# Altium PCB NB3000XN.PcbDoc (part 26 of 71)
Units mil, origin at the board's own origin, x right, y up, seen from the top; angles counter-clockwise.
Board outline 9527.56 x 6929.77 mil, 6 copper layers (Top Layer, GND+SHIELD, MidLayer1, MidLayer2, P2 - 3V3+5V0, Bottom Layer), stack 62.375 mil thick; 832 components, 1027 nets, 4655 pads, 4981 vias.
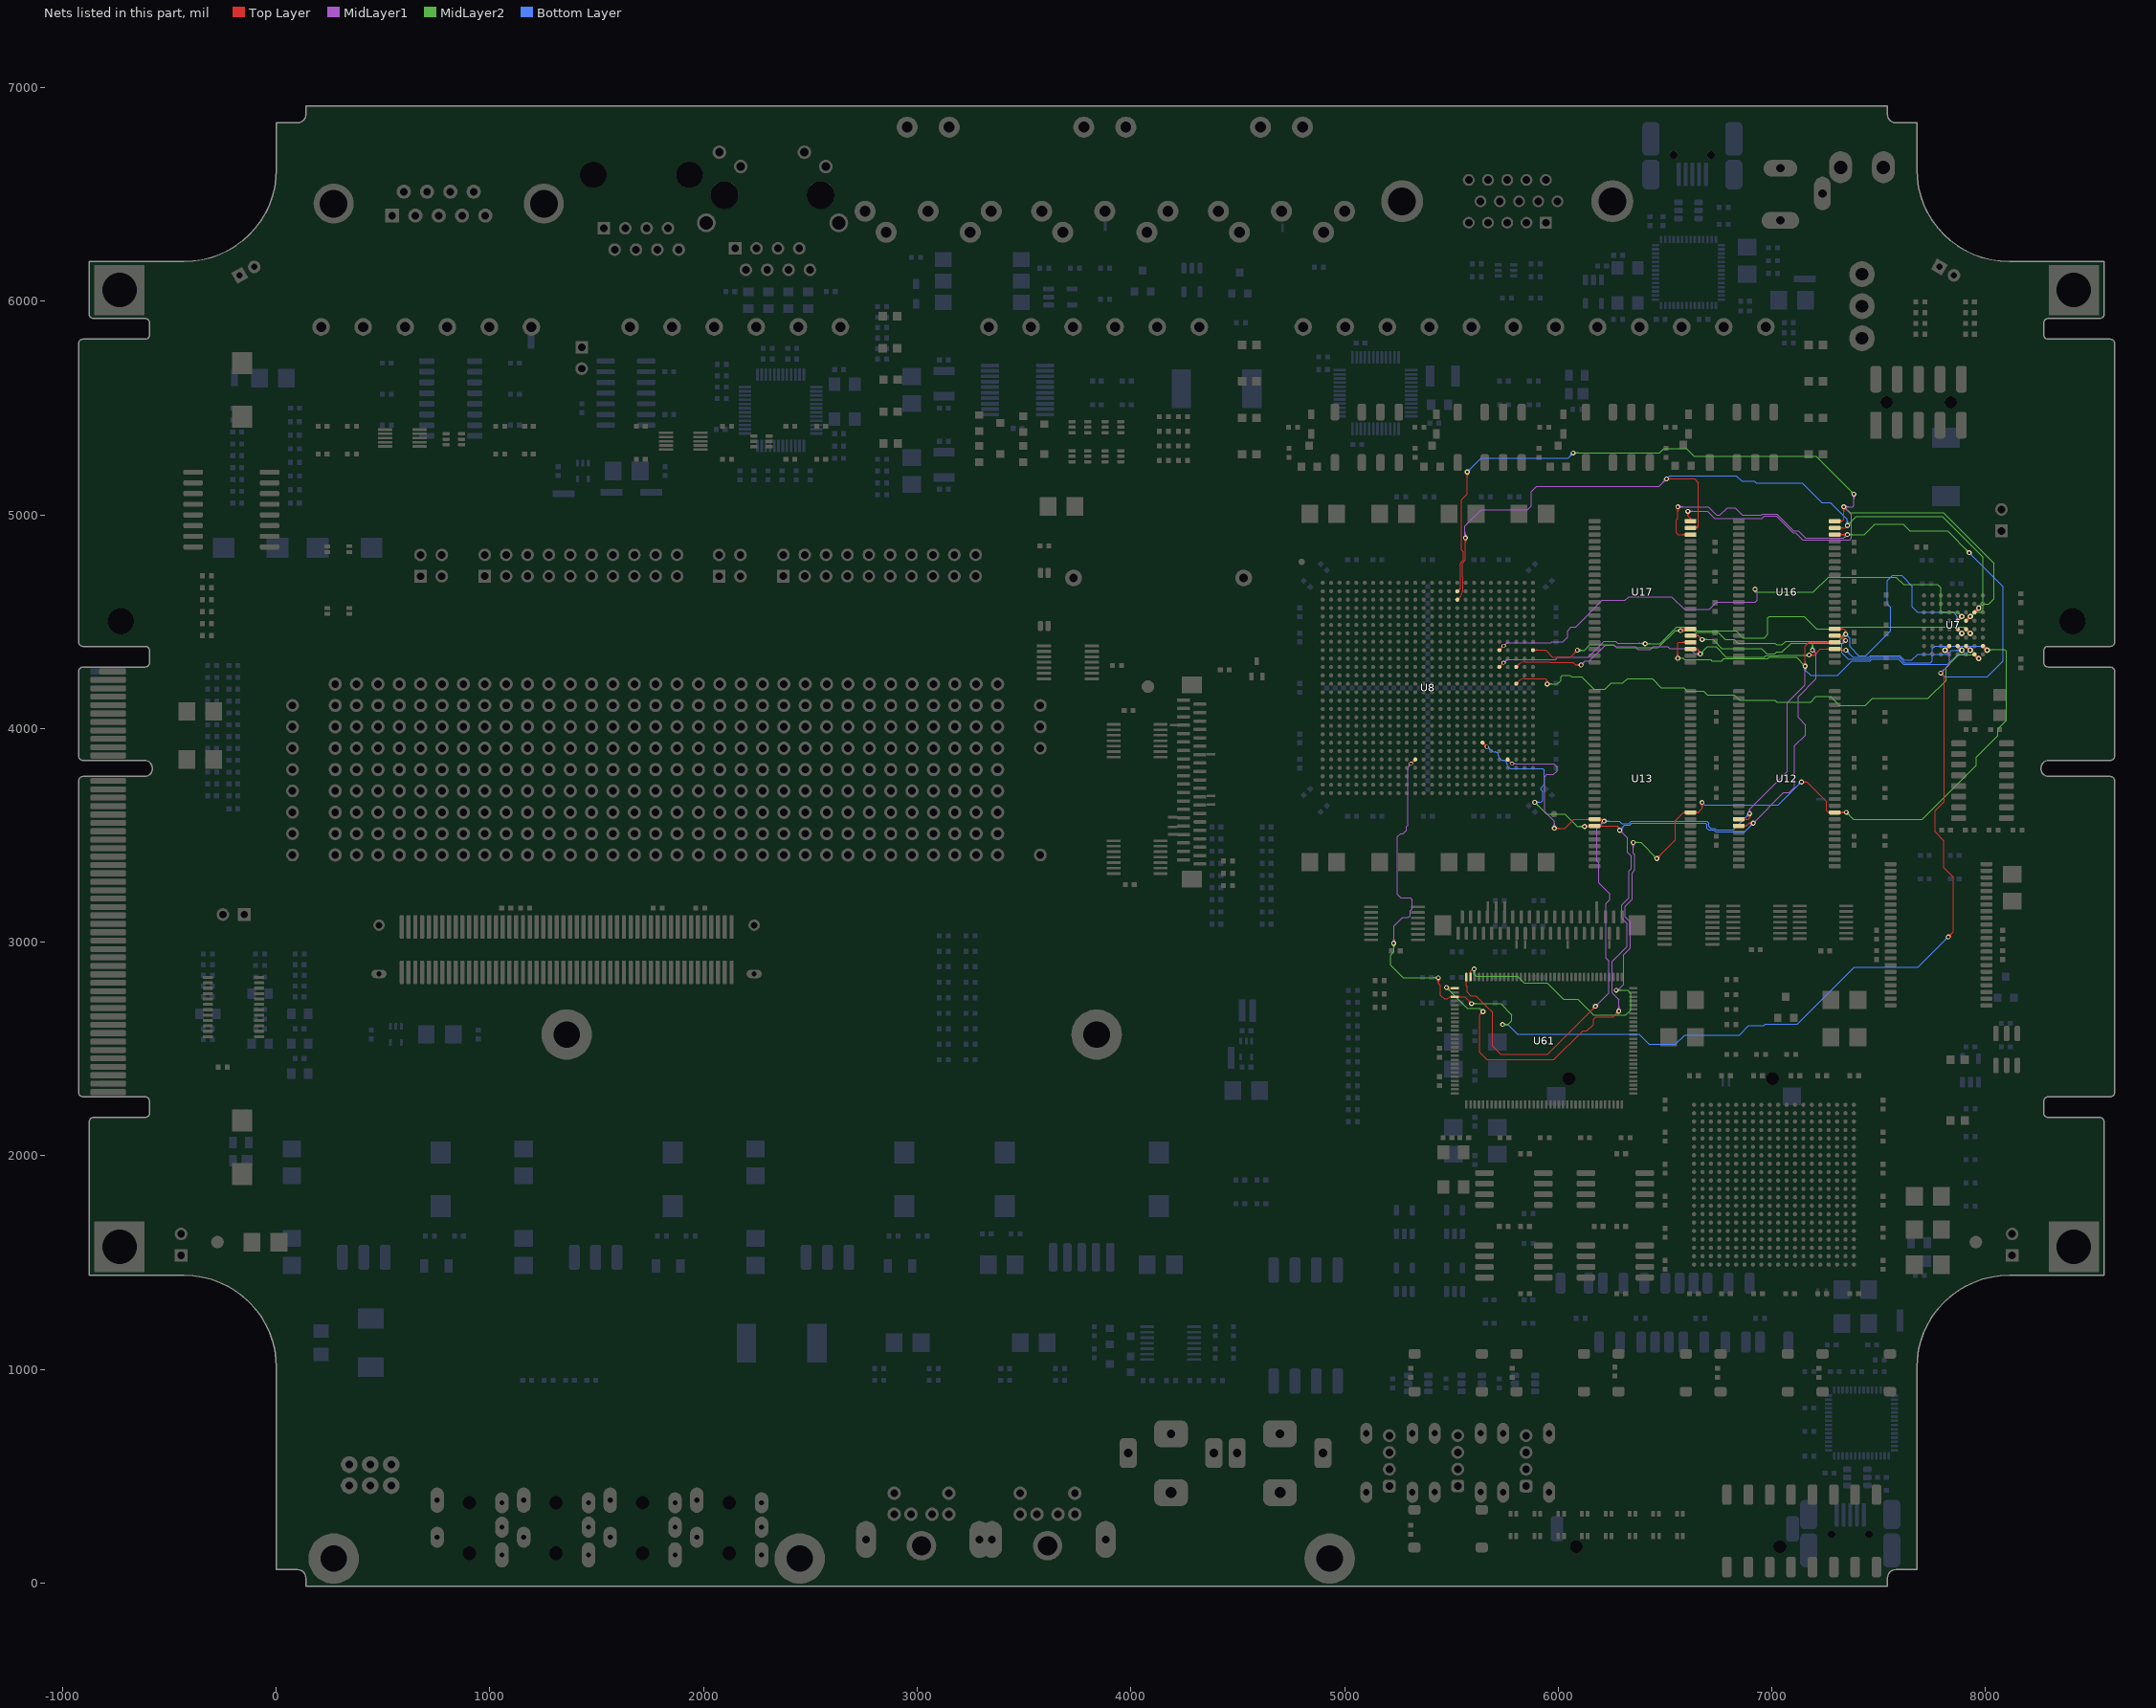
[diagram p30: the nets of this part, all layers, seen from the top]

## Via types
v1: diameter 23, hole 11.81, Top Layer to Bottom Layer, 3672 vias
v2: diameter 26, hole 11.81, Top Layer to Bottom Layer, 461 vias
v3: diameter 19, hole 11.81, Top Layer to Bottom Layer, tented both sides, 396 vias
v4: diameter 23.62, hole 11.81, Top Layer to Bottom Layer, 288 vias
v5: diameter 20, hole 11.81, Top Layer to Bottom Layer, 91 vias
v6: diameter 23, hole 11.81, Top Layer to Bottom Layer, tented both sides, 50 vias
v7: diameter 31, hole 11.81, Top Layer to Bottom Layer, 15 vias
v8: diameter 27.56, hole 11.81, Top Layer to Bottom Layer, tented both sides, 4 vias
v9: diameter 29, hole 11.81, Top Layer to Bottom Layer, 3 vias
v10: diameter 21, hole 11.81, Top Layer to Bottom Layer, 1 vias

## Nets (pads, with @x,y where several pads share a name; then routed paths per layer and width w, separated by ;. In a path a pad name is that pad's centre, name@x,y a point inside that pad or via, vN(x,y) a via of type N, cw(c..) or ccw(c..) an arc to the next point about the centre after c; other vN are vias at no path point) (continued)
DB_MEM.BUS_A14: U7.A7 U8.L24 U12.36 U13.36 U16.25 U17.25 U61.101 | length 8477.1
  Top Layer w4: U61.101@5586.86,2853.36 ccw(c5580.03,2860.19) 5589.69,2860.19 ccw(c5599.34,2860.19) U61.101@5592.51,2853.36 ; U61.101@5589.68,2837.34 5589.69,2866.2 5598.52,2875.04 v1(5606.86,2875.04) ; 5589.98,2866.5 cw(c5600.15,2856.33) v1@5605,2869.86 ; 5594.44,2870.96 cw(c5602.5,2862.9) v1@5606.35,2873.63 ; U8.L24@5803.39,4295.77 ccw(c5803.39,4313.49) 5815.92,4300.96 ; U8.L24@5810.73,4288.43 cw(c5828.45,4288.43) 5815.92,4300.96 ; 5924.74,4312.29 5920,4312.29 ; v1@6100.14,4290.99 ccw(c6083.92,4274.77) 6083.92,4297.71 ccw(c6083.92,4320.64) v1@6100.14,4304.43 ; v1@6102.97,4293.82 ccw(c6093.58,4284.43) 6093.58,4297.71 ccw(c6093.58,4310.99) v1@6102.97,4301.6 ; v1(6106.86,4297.71) 6081.16,4297.71 6070,4308.87 5965.11,4308.87 5961.69,4312.29 5920,4312.29 ; v1(6461.86,3391.71) 6548.52,3478.37 6548.52,3568.52 6587.52,3607.52 ; v1@6461.86,3397.21 ccw(c6461.86,3410.49) 6471.25,3401.1 ccw(c6480.64,3391.71) v1@6467.36,3391.71 ; v1@6461.86,3401.21 ccw(c6461.86,3424.14) 6478.07,3407.93 ccw(c6494.29,3391.71) v1@6471.36,3391.71 ; U13.36@6595.04,3603.32 ccw(c6587.52,3598.69) 6587.52,3607.52 ; U13.36@6595.04,3611.72 cw(c6587.52,3616.35) 6587.52,3607.52 ; U17.25@6619.41,4372.28 6650.95,4372.28 ; U13.36@6642.91,3602.16 cw(c6654.97,3591.27) 6654.97,3607.52 ; U13.36@6642.91,3612.88 ccw(c6654.97,3623.77) 6654.97,3607.52 ; U17.25@6643.87,4368.23 cw(c6650.95,4364.07) 6650.95,4372.28 ; U17.25@6643.87,4376.34 ccw(c6650.95,4380.5) 6650.95,4372.28 ; 6652.31,4370.92 cw(c6634,4352.61) v1@6659.73,4349.67 ; 6658.17,4365.06 cw(c6644.52,4351.41) v1@6663.7,4349.21 ; v1(6665.19,4349.04) 6665.19,4358.04 6650.95,4372.28 ; v1@6666.81,3647.66 cw(c6650.59,3631.44) 6673.52,3631.44 cw(c6696.46,3631.44) v1@6680.24,3647.66 ; v1@6669.64,3650.49 cw(c6660.25,3641.1) 6673.52,3641.1 cw(c6686.8,3641.1) v1@6677.41,3650.49 ; v1(6673.52,3654.37) 6673.52,3626.07 6654.97,3607.52 ; v1(7138.52,3750.04) 7165.19,3750.04 7256.86,3658.37 7256.86,3615.52 7264.86,3607.52 ; v1@7142.41,3746.15 cw(c7151.8,3736.76) 7151.8,3750.04 cw(c7151.8,3763.32) v1@7142.41,3753.93 ; v1@7145.24,3743.32 cw(c7161.46,3727.11) 7161.46,3750.04 cw(c7161.46,3772.98) v1@7145.24,3756.76 ; v1(7174.19,4344.37) 7200,4344.37 7227.91,4372.28 U16.25@7294.41,4372.28 U16.25@7298.52,4372.28 ; v1@7178.08,4340.49 cw(c7187.47,4331.1) 7187.47,4344.37 cw(c7187.47,4357.65) v1@7178.08,4348.26 ; v1@7180.91,4337.66 cw(c7197.13,4321.44) 7197.13,4344.37 cw(c7197.13,4367.31) v1@7180.91,4351.09 ; U12.36@7269.46,3604.45 ccw(c7264.86,3602.53) 7264.86,3607.52 ; U12.36@7269.46,3610.59 cw(c7264.86,3612.51) 7264.86,3607.52 ; U16.25@7271.19,4366.63 ccw(c7257.54,4352.97) 7257.54,4372.28 ccw(c7257.54,4391.6) U16.25@7271.19,4377.94 ; U16.25@7298.52,4366.71 U16.25@7298.52,4372.28 ; U12.36@7317.63,3601.86 cw(c7331.28,3588.21) 7331.28,3607.52 cw(c7331.28,3626.83) U12.36@7317.63,3613.18 ; U16.25@7319.2,4368.86 cw(c7324.61,4366.29) 7324.61,4372.28 ; U16.25@7319.2,4375.71 ccw(c7324.61,4378.28) 7324.61,4372.28 ; 7323.52,3607.52 ccw(c7323.52,3633.37) v1@7341.81,3615.09 ; 7327.65,3607.52 cw(c7327.65,3587.5) v1@7341.81,3601.66 ; 7333.18,3607.52 ccw(c7333.18,3623.72) v1@7344.64,3612.26 ; v1@7337.85,4362.16 ccw(c7330.19,4357.98) 7330.19,4366.71 ; v1@7337.85,4371.26 cw(c7330.19,4375.43) 7330.19,4366.71 ; v1(7346.19,4366.71) 7330.19,4366.71 ; v1(7348.52,3608.37) 7338.19,3608.37 7337.34,3607.52 U12.36@7294.41,3607.52 7264.86,3607.52 ; 5815.92,4300.96 cw(c5843.27,4273.61) 5843.27,4312.29 5910,4312.29 5920,4312.29 ; 6587.52,3607.52 6615,3607.52 6654.97,3607.52 ; U16.25@7298.52,4372.28 7324.62,4372.28 ; 7324.62,4372.28 7330.19,4366.71
  Top Layer w8: U7.A7@7987.8,4380.57 cw(c7987.8,4366.09) 7998.04,4376.33 cw(c8008.28,4386.57) U7.A7@7993.8,4386.57 ; U7.A7@7987.8,4386.57 v2(8007.48,4366.89) ; v2@7998.48,4366.89 ccw(c7976.75,4366.89) 7992.12,4382.25 ccw(c8007.48,4397.62) v2@8007.48,4375.89
  MidLayer1 w4: v1(6106.86,4297.71) 6125.86,4316.71 6146.15,4316.71 6220.48,4391.04 6260.19,4391.04 6268.19,4383.04 6359.86,4383.04 6372.52,4370.37 6431.86,4370.37 6444.86,4383.37 6512.82,4383.37 6521.15,4375.04 6615.19,4375.04 6641.19,4349.04 v1(6665.19,4349.04) ; v1@6106.86,4303.21 ccw(c6106.86,4316.49) 6116.25,4307.1 ccw(c6125.64,4297.71) v1@6112.36,4297.71 ; v1@6106.86,4307.21 ccw(c6106.86,4330.14) 6123.07,4313.93 ccw(c6139.29,4297.71) v1@6116.36,4297.71 ; v1(6271.52,2775.04) 6279.19,2775.04 6306.86,2802.71 6306.86,2942.06 6337.52,2972.73 6337.52,3094 6313.19,3118.34 6313.19,3168.41 6346.86,3202.08 6346.86,3325.04 6359.19,3337.37 6359.19,3409.02 6350.86,3417.35 v1(6350.86,3466.71) ; v1@6344.14,3459.99 cw(c6327.92,3443.77) 6350.86,3443.77 cw(c6373.79,3443.77) v1@6357.57,3459.99 ; v1@6346.97,3462.82 cw(c6337.58,3453.43) 6350.86,3453.43 cw(c6364.14,3453.43) v1@6354.75,3462.82 ; v1@6658.47,4342.32 ccw(c6642.26,4326.11) 6642.26,4349.04 ccw(c6642.26,4371.98) v1@6658.47,4355.76 ; v1@6661.3,4345.15 ccw(c6651.91,4335.76) 6651.91,4349.04 ccw(c6651.91,4362.32) v1@6661.3,4352.93
  MidLayer2 w4: v1@5600.14,2868.32 cw(c5583.92,2852.11) 5606.86,2852.11 cw(c5629.79,2852.11) v1@5613.57,2868.32 ; v1@5602.97,2871.15 cw(c5593.58,2861.76) 5606.86,2861.76 cw(c5620.14,2861.76) v1@5610.75,2871.15 ; v1(5606.86,2875.04) 5606.86,2851.69 5617.17,2841.37 5808.56,2841.37 5841.56,2808.37 5948.52,2808.37 6023.52,2733.37 6091.52,2733.37 6166.52,2658.37 6316.52,2658.37 6340.19,2682.04 6340.19,2758.37 6323.52,2775.04 v1(6271.52,2775.04) ; v1@6275.41,2771.15 cw(c6284.8,2761.76) 6284.8,2775.04 cw(c6284.8,2788.32) v1@6275.41,2778.93 ; v1@6278.24,2768.32 cw(c6294.46,2752.11) 6294.46,2775.04 cw(c6294.46,2797.98) v1@6278.24,2781.76 ; v1(6350.86,3466.71) 6386.86,3466.71 v1(6461.86,3391.71) ; v1@6354.75,3462.82 cw(c6364.14,3453.43) 6364.14,3466.71 cw(c6364.14,3479.99) v1@6354.75,3470.6 ; v1@6357.57,3459.99 cw(c6373.79,3443.77) 6373.79,3466.71 cw(c6373.79,3489.64) v1@6357.57,3473.43 ; v1@6452.36,3391.71 ccw(c6429.42,3391.71) 6445.64,3407.93 ccw(c6461.86,3424.14) v1@6461.86,3401.21 ; v1@6456.36,3391.71 ccw(c6443.08,3391.71) 6452.47,3401.1 ccw(c6461.86,3410.49) v1@6461.86,3397.21 ; v1(6665.19,4349.04) 6699.52,4383.37 6738.19,4383.37 6786.86,4334.71 6965.19,4334.71 6972.19,4341.71 7032.52,4341.71 7035.19,4344.37 v1(7174.19,4344.37) ; v1@6665.19,4354.54 ccw(c6665.19,4367.82) 6674.58,4358.43 ccw(c6683.97,4349.04) v1@6670.69,4349.04 ; v1@6665.19,4358.54 ccw(c6665.19,4381.48) 6681.41,4365.26 ccw(c6697.63,4349.04) v1@6674.69,4349.04 ; v1@7167.47,4337.66 ccw(c7151.26,4321.44) 7151.26,4344.37 ccw(c7151.26,4367.31) v1@7167.47,4351.09 ; v1@7170.3,4340.49 ccw(c7160.91,4331.1) 7160.91,4344.37 ccw(c7160.91,4357.65) v1@7170.3,4348.26 ; v1@7348.52,3598.87 cw(c7348.52,3575.94) 7364.74,3592.16 cw(c7380.96,3608.37) v1@7358.02,3608.37 ; v1@7348.52,3602.87 cw(c7348.52,3589.6) 7357.91,3598.99 cw(c7367.3,3608.37) v1@7354.02,3608.37 ; v1(7348.52,3608.37) 7373.52,3583.37 7382.52,3574.37 7703.21,3574.37 7712.21,3583.37 7956.86,3828.02 7956.86,3867.04 8056.86,3967.04 8056.86,3998.26 8098.52,4039.92 8098.52,4360.85 8090,4369.37 8009.97,4369.37 v2(8007.48,4366.89) ; v2@8009.6,4364.77 cw(c8020.72,4353.65) 8020.72,4369.37 ; v2@8012.43,4361.94 cw(c8030.38,4343.99) 8030.38,4369.37 ; v2@8015.26,4359.11 cw(c8040.04,4334.33) 8040.04,4369.37 ; v2@8015.26,4374.67 ccw(c8028.04,4387.45) 8028.04,4369.37
  Bottom Layer w4: v1(6673.52,3654.37) 6686.19,3641.71 7030.19,3641.71 v1(7138.52,3750.04) ; v1@7129.02,3750.04 cw(c7106.09,3750.04) 7122.31,3733.82 cw(c7138.52,3717.61) v1@7138.52,3740.54 ; v1@7133.02,3750.04 cw(c7119.75,3750.04) 7129.14,3740.65 cw(c7138.52,3731.26) v1@7138.52,3744.54 ; v1@7346.19,4357.21 cw(c7346.19,4334.27) 7362.41,4350.49 cw(c7378.63,4366.71) v1@7355.69,4366.71 ; v1@7346.19,4361.21 cw(c7346.19,4347.93) 7355.58,4357.32 cw(c7364.97,4366.71) v1@7351.69,4366.71 ; v1(7346.19,4366.71) 7379.52,4333.37 7453.9,4333.37 7462.23,4341.71 7598.47,4341.71 7619.8,4320.37 7655.52,4320.37 7682.86,4347.71 7740.86,4347.71 7751.52,4358.37 7751.52,4375.04 7763.52,4387.04 7987.33,4387.04 v2(8007.48,4366.89)
DB_MEM.BUS_A15: U7.C7 U8.AB23 U12.20 U13.20 U16.26 U17.26 U61.102 | length 7628.8
  Top Layer w4: U61.102@5567.17,2821.32 cw(c5560.34,2814.49) 5570,2814.49 cw(c5579.66,2814.49) U61.102@5572.83,2821.32 ; U61.102@5570,2837.34 5570,2795.23 5573.52,2791.71 5573.52,2766.71 5590.19,2750.04 5615.19,2750.04 5664.47,2700.76 5693,2672.23 5693,2513.31 5731.31,2475 5785,2475 5949.52,2475.04 v1(6174.52,2700.04) ; U8.AB23@5764.02,3847.85 cw(c5764.02,3829.75) 5776.82,3842.55 cw(c5789.62,3855.35) U8.AB23@5771.52,3855.35 ; U8.AB23@5764.02,3848.01 cw(c5764.02,3830.29) 5776.55,3842.82 cw(c5789.08,3855.35) U8.AB23@5771.36,3855.35 ; U8.AB23@5764.02,3855.35 v3(5783.7,3835.67) ; v1(5981.86,3533.37) 6030.33,3533.37 6072.98,3576.02 U13.20@6170.59,3576.02 ; v1@5985.75,3529.49 cw(c5995.14,3520.1) 5995.14,3533.37 cw(c5995.14,3546.65) v1@5985.75,3537.26 ; v1@5988.57,3526.66 cw(c6004.79,3510.44) 6004.79,3533.37 cw(c6004.79,3556.31) v1@5988.57,3540.09 ; U13.20@6147.37,3570.37 ccw(c6133.72,3556.71) 6133.72,3576.02 ccw(c6133.72,3595.34) U13.20@6147.37,3581.68 ; v1@6165.02,2700.04 cw(c6142.09,2700.04) 6158.31,2683.82 cw(c6174.52,2667.61) v1@6174.52,2690.54 ; v1@6169.02,2700.04 cw(c6155.75,2700.04) 6165.14,2690.65 cw(c6174.52,2681.26) v1@6174.52,2694.54 ; U13.20@6180.08,3576.04 cw(c6180.08,3532.57) v1@6211.25,3562.87 ; U13.20@6189.55,3576.04 cw(c6189.55,3541.77) v1@6214.11,3565.66 ; U13.20@6194.14,3581.32 ccw(c6205.86,3591.67) 6205.86,3576.04 ; U13.20@6194.16,3570.75 cw(c6205.86,3560.48) 6205.86,3576.04 ; 6199.02,3576.04 cw(c6199.02,3550.98) v1@6216.98,3568.45 ; v1@6208.38,3560.09 ccw(c6170.61,3523.36) 6170.61,3576.04 6205.86,3576.04 ; v1(6215.19,3566.71) 6205.86,3576.04 ; v1@6552.81,4335.76 ccw(c6536.59,4351.98) 6559.52,4351.98 ccw(c6582.46,4351.98) v1@6566.24,4335.76 ; v1@6555.64,4332.93 ccw(c6546.25,4342.32) 6559.52,4342.32 ccw(c6572.8,4342.32) v1@6563.41,4332.93 ; v1(6559.52,4329.04) 6559.52,4399.52 6563.78,4403.78 U17.26@6619.41,4403.78 ; U17.26@6596.19,4398.12 ccw(c6582.54,4384.47) 6582.54,4403.78 ccw(c6582.54,4423.09) U17.26@6596.19,4409.44 ; U12.20@6845.59,3576.02 6891.02,3576.02 6896.19,3581.19 ; U12.20@6868.81,3570.37 cw(c6882.46,3556.71) 6882.46,3576.02 cw(c6882.46,3595.34) U12.20@6868.81,3581.68 ; v1@6890.04,3594.46 cw(c6878.79,3581.19) 6896.19,3581.19 ; v1@6892.63,3597.51 cw(c6886.11,3589.83) 6896.19,3589.83 cw(c6906.27,3589.83) v1@6899.75,3597.51 ; v1(6896.19,3601.71) 6896.19,3581.19 ; v1@6902.34,3594.46 ccw(c6913.59,3581.19) 6896.19,3581.19 ; v1@7149.47,4298.43 ccw(c7133.26,4314.64) 7156.19,4314.64 ccw(c7179.13,4314.64) v1@7162.91,4298.43 ; v1@7152.3,4295.6 ccw(c7142.91,4304.99) 7156.19,4304.99 ccw(c7169.47,4304.99) v1@7160.08,4295.6 ; v1(7156.19,4291.71) 7156.19,4386.19 7173.78,4403.78 U16.26@7294.41,4403.78 ; U16.26@7271.19,4398.12 ccw(c7257.54,4384.47) 7257.54,4403.78 ccw(c7257.54,4423.09) U16.26@7271.19,4409.44 ; 5770.9,3848.47 cw(c5758.09,3835.67) 5776.2,3835.67 ccw(c5758.09,3835.67) 5770.9,3848.47 ; 5770.9,3848.47 ccw(c5783.7,3861.28) 5783.7,3843.17 cw(c5783.7,3861.28) 5770.9,3848.47
  Top Layer w8: U7.C7@7909.06,4380.57 cw(c7909.06,4366.09) 7919.3,4376.33 cw(c7929.54,4386.57) U7.C7@7915.06,4386.57 ; U7.C7@7909.06,4386.57 v2(7928.74,4366.89) ; v2@7919.74,4366.89 ccw(c7898.01,4366.89) 7913.38,4382.25 ccw(c7928.74,4397.62) v2@7928.74,4375.89
  MidLayer1 w4: v3(5783.7,3835.67) 5861.38,3835.67 5910,3835.67 5920,3835.67 5924.74,3835.67 5979.08,3835.67 5995,3819.74 5995,3802.12 5977.88,3785 5946.86,3785 5936.86,3775 5936.86,3611.71 5981.86,3566.71 v1(5981.86,3533.37) ; v3@5788.89,3830.48 cw(c5801.43,3817.94) 5801.43,3835.67 cw(c5801.43,3853.4) v3@5788.89,3840.86 ; v1@5975.14,3540.09 ccw(c5958.92,3556.31) 5981.86,3556.31 ccw(c6004.79,3556.31) v1@5988.57,3540.09 ; v1@5977.97,3537.26 ccw(c5968.58,3546.65) 5981.86,3546.65 ccw(c5995.14,3546.65) v1@5985.75,3537.26 ; v1(6174.52,2700.04) 6236.86,2762.37 6236.86,2913.04 6223.52,2926.37 6223.52,3180.71 6242.86,3200.04 6242.86,3225.04 6190.19,3277.71 6190.19,3372.06 6181.86,3380.39 6181.86,3533.37 v1(6215.19,3566.71) ; v1@6174.52,2705.54 ccw(c6174.52,2718.82) 6183.91,2709.43 ccw(c6193.3,2700.04) v1@6180.02,2700.04 ; v1@6174.52,2709.54 ccw(c6174.52,2732.48) 6190.74,2716.26 ccw(c6206.96,2700.04) v1@6184.02,2700.04 ; v1@6205.69,3566.71 cw(c6182.76,3566.71) 6198.97,3550.49 cw(c6215.19,3534.27) v1@6215.19,3557.21 ; v1@6209.69,3566.71 cw(c6196.41,3566.71) 6205.8,3557.32 cw(c6215.19,3547.93) v1@6215.19,3561.21 ; v1@6889.92,3608.84 ccw(c6877.73,3622.71) 6896.19,3622.71 ; v1@6892.56,3605.84 ccw(c6885.5,3613.87) 6896.19,3613.87 ccw(c6906.88,3613.87) v1@6899.82,3605.84 ; v1(6896.19,3601.71) 6896.19,3622.71 ; v1@6902.46,3608.84 cw(c6914.65,3622.71) 6896.19,3622.71 ; v1@7149.47,4284.99 cw(c7133.26,4268.77) 7156.19,4268.77 cw(c7179.13,4268.77) v1@7162.91,4284.99 ; v1@7152.3,4287.82 cw(c7142.91,4278.43) 7156.19,4278.43 cw(c7169.47,4278.43) v1@7160.08,4287.82 ; 7155,4245 7155,4203.54 7073.52,4122.06 7073.52,3800.04 6896.19,3622.71 ; 7156.19,4245 v1(7156.19,4291.71) ; 5801.81,3835.67 cw(c5801.81,3853.78) 5789,3840.97 ccw(c5801.81,3853.78) 5801.81,3835.67 ; 5801.81,3835.67 ccw(c5801.81,3817.56) 5789,3830.37 cw(c5801.81,3817.56) 5801.81,3835.67
  MidLayer2 w4: v1(6559.52,4329.04) 6584.33,4329.04 6590,4323.37 6713.52,4323.37 6719.52,4317.37 6765.19,4317.37 6774.52,4326.71 6981.86,4326.71 6988.52,4333.37 7114.52,4333.37 v1(7156.19,4291.71) ; v1@6563.41,4325.15 cw(c6572.8,4315.76) 6572.8,4329.04 cw(c6572.8,4342.32) v1@6563.41,4332.93 ; v1@6566.24,4322.32 cw(c6582.46,4306.11) 6582.46,4329.04 cw(c6582.46,4351.98) v1@6566.24,4335.76 ; v1@7146.69,4291.71 ccw(c7123.76,4291.71) 7139.97,4307.93 ccw(c7156.19,4324.14) v1@7156.19,4301.21 ; v1@7150.69,4291.71 ccw(c7137.41,4291.71) 7146.8,4301.1 ccw(c7156.19,4310.49) v1@7156.19,4297.21
  Bottom Layer w4: v1(6215.19,3566.71) 6287.52,3566.71 6298.52,3555.71 6331.86,3555.71 6342.86,3566.71 6696.86,3566.71 6705.19,3558.37 6705.19,3541.71 6713.52,3533.37 6731.48,3533.37 6739.82,3525.04 6819.52,3525.04 v1(6896.19,3601.71) ; v1@6219.08,3562.82 cw(c6228.47,3553.43) 6228.47,3566.71 cw(c6228.47,3579.99) v1@6219.08,3570.6 ; v1@6221.91,3559.99 cw(c6238.13,3543.77) 6238.13,3566.71 cw(c6238.13,3589.64) v1@6221.91,3573.43 ; v1@6886.69,3601.71 cw(c6863.76,3601.71) 6879.97,3585.49 cw(c6896.19,3569.27) v1@6896.19,3592.21 ; v1@6890.69,3601.71 cw(c6877.41,3601.71) 6886.8,3592.32 cw(c6896.19,3582.93) v1@6896.19,3596.21 ; v1@7151.35,4283.53 cw(c7146.32,4275.04) 7156.19,4275.04 ; v1(7156.19,4291.71) 7156.19,4275.04 ; v1@7161.03,4283.53 ccw(c7166.06,4275.04) 7156.19,4275.04 ; v2(7928.74,4366.89) 7915.88,4354.03 7903.85,4354.03 7897.52,4347.71 7871.19,4347.71 7823.52,4300.04 7617.51,4300.04 7592.55,4325 7575,4325 7468.19,4325.04 7459.86,4316.71 7375.19,4316.71 7308.52,4250.04 7181.19,4250.04 7156.19,4275.04
DB_MEM.BUS_A16: U7.D7 U8.Y20 U12.21 U13.21 U16.27 U17.27 U61.103 | length 8294.5
  Top Layer w4: v1@5477.92,2789.44 ccw(c5490.8,2802.31) 5490.8,2784.1 ; v1@5480.75,2792.26 ccw(c5500.45,2811.97) U61.103@5500.45,2784.1 ; v1@5481.13,2784.1 U61.103@5516.83,2784.1 ; v1@5483.57,2781.66 cw(c5489.47,2775.76) 5489.47,2784.1 ; v1@5483.57,2795.09 ccw(c5510.11,2821.63) U61.103@5510.11,2784.1 ; U61.103@5500.81,2781.27 ccw(c5493.98,2774.44) 5493.98,2784.1 ccw(c5493.98,2793.76) U61.103@5500.81,2786.93 ; v1@5639.02,2675.04 cw(c5616.09,2675.04) 5632.31,2658.82 cw(c5648.52,2642.61) v1@5648.52,2665.54 ; v1@5643.02,2675.04 cw(c5629.75,2675.04) 5639.13,2665.65 cw(c5648.52,2656.26) v1@5648.52,2669.54 ; U8.Y20@5645.91,3926.59 cw(c5645.91,3908.49) 5658.71,3921.29 cw(c5671.51,3934.09) U8.Y20@5653.41,3934.09 ; U8.Y20@5645.91,3926.75 cw(c5645.91,3909.03) 5658.44,3921.56 cw(c5670.97,3934.09) U8.Y20@5653.25,3934.09 ; U8.Y20@5645.91,3934.09 v3(5665.59,3914.41) ; v1(5648.52,2675.04) 5631.86,2658.37 5631.86,2485.37 5667.19,2450.04 5980.5,2450.04 6115.29,2584.82 6134.82,2584.82 6165.19,2615.19 6165.19,2638.73 6176.5,2650.04 6256.86,2650.04 v1(6283.86,2677.04) ; v1(6123.52,3541.71) 6170.59,3541.71 6173.52,3541.71 U13.21@6173.52,3544.53 ; v1@6126.91,3541.71 ccw(c6126.91,3570.65) U13.21@6147.37,3550.18 ; v1@6127.41,3537.82 cw(c6136.8,3528.43) 6136.8,3541.71 cw(c6136.8,3554.99) v1@6127.41,3545.6 ; v1@6130.24,3534.99 cw(c6146.46,3518.77) 6146.46,3541.71 cw(c6146.46,3564.64) v1@6130.24,3548.43 ; 6136.57,3541.71 ccw(c6136.57,3560.99) U13.21@6150.2,3547.36 ; 6140.53,3541.71 cw(c6140.53,3532.02) U13.21@6147.37,3538.87 ; U13.21@6170.59,3544.53 6179.53,3544.53 U13.21@6180,3545 ; U13.21@6180,3544.53 6275.71,3544.53 6287.86,3532.37 v1(6287.86,3524.04) ; U13.21@6193.81,3538.87 cw(c6207.46,3525.22) 6207.46,3544.53 cw(c6207.47,3563.84) U13.21@6193.81,3550.18 ; v1@6274.36,2677.04 cw(c6251.42,2677.04) 6267.64,2660.82 cw(c6283.86,2644.61) v1@6283.86,2667.54 ; 6276.86,3543.37 cw(c6262.46,3528.96) v1@6282.46,3525.09 ; v1@6278.36,2677.04 cw(c6265.08,2677.04) 6274.47,2667.65 cw(c6283.86,2658.26) v1@6283.86,2671.54 ; 6282.19,3538.05 cw(c6271.37,3527.23) v1@6286.38,3524.33 ; U17.27@6619.41,4435.28 6655.62,4435.28 ; U17.27@6642.76,4429.76 cw(c6655.62,4417.53) 6655.62,4435.28 ; U17.27@6642.76,4440.79 ccw(c6655.62,4453.02) 6655.62,4435.28 ; v1@6664.69,4416.71 ccw(c6641.76,4416.71) 6657.97,4432.93 ccw(c6674.19,4449.14) v1@6674.19,4426.21 ; v1@6668.69,4416.71 ccw(c6655.41,4416.71) 6664.8,4426.1 ccw(c6674.19,4435.49) v1@6674.19,4422.21 ; v1(6674.19,4416.71) 6655.62,4435.28 ; U12.21@6845.59,3544.53 6880,3544.53 ; U12.21@6869.35,3539.47 cw(c6880,3530.78) 6880,3544.53 ; U12.21@6869.35,3549.58 ccw(c6880,3558.27) 6880,3544.53 ; v1@6905.5,3551.37 ccw(c6892.85,3541.05) 6892.85,3557.37 ccw(c6892.85,3573.69) v1@6905.5,3563.38 ; v1@6908.6,3553.9 ccw(c6901.27,3547.93) 6901.27,3557.37 ccw(c6901.27,3566.82) v1@6908.6,3560.85 ; v1(6912.86,3557.37) 6892.85,3557.37 6880,3544.53 ; U16.27@7294.41,4435.28 7323.97,4435.28 ; U16.27@7311.97,4427.28 cw(c7311.97,4378.99) v1@7346.11,4413.13 ; U16.27@7311.97,4431.28 cw(c7311.97,4392.65) v1@7339.28,4419.96 ; U16.27@7311.97,4439.28 cw(c7311.97,4419.96) 7325.63,4433.62 ; U16.27@7314.71,4432.37 cw(c7320.79,4425.92) 7327.06,4432.19 ; U16.27@7317.46,4429.46 cw(c7323.62,4422.93) 7329.97,4429.28 ; U16.27@7319.35,4432.2 cw(c7323.97,4430.28) 7323.97,4435.28 ; U16.27@7319.35,4438.35 ccw(c7323.97,4440.27) 7323.97,4435.28 ; 7324.14,4435.1 ccw(c7317.97,4428.92) 7311.97,4435.28 cw(c7311.97,4406.31) 7332.45,4426.79 ; 7327.55,4431.69 cw(c7307.9,4412.04) v1@7335.69,4412.04 ; 7332.41,4426.84 ccw(c7345.19,4439.62) v1@7345.19,4421.54 ; 7334.38,4424.86 cw(c7321.55,4412.04) v1@7339.69,4412.04 ; v1(7345.19,4412.04) 7345.19,4414.05 7323.97,4435.28 ; 5652.79,3927.21 cw(c5639.98,3914.41) 5658.09,3914.41 ccw(c5639.98,3914.41) 5652.79,3927.21 ; 5652.79,3927.21 ccw(c5665.59,3940.02) 5665.59,3921.91 cw(c5665.59,3940.02) 5652.79,3927.21
  Top Layer w8: U7.D7@7869.69,4380.57 cw(c7869.69,4366.09) 7879.93,4376.33 cw(c7890.17,4386.57) U7.D7@7875.69,4386.57 ; U7.D7@7869.69,4386.57 v2(7889.37,4366.89) ; v2@7880.37,4366.89 ccw(c7858.64,4366.89) 7874.01,4382.25 ccw(c7889.37,4397.62) v2@7889.37,4375.89
  MidLayer1 w4: v1@6277.14,2683.76 ccw(c6260.92,2699.98) 6283.86,2699.98 ccw(c6306.79,2699.98) v1@6290.57,2683.76 ; v1@6279.97,2680.93 ccw(c6270.58,2690.32) 6283.86,2690.32 ccw(c6297.14,2690.32) v1@6287.75,2680.93 ; v1(6283.86,2677.04) 6283.86,2731.14 6252.86,2762.14 6252.86,2910.71 6321.52,2979.37 6321.52,3087.37 6297.19,3111.71 6297.19,3175.04 6330.86,3208.71 6330.86,3332.69 6343.19,3345.02 6343.19,3402.39 6323.86,3421.73 6323.86,3488.04 v1(6287.86,3524.04) ; v1@6287.86,3514.54 cw(c6287.86,3491.61) 6304.07,3507.82 cw(c6320.29,3524.04) v1@6297.36,3524.04 ; v1@6287.86,3518.54 cw(c6287.86,3505.26) 6297.25,3514.65 cw(c6306.64,3524.04) v1@6293.36,3524.04 ; v1(6912.86,3557.37) 7055.52,3700.04 7081.86,3700.04 7106.86,3725.04 7106.86,3919.34 7157.52,3970 7157.52,4017.48 7123.52,4051.48 7123.52,4149.43 7206.86,4232.77 7206.86,4350.04 v1(7190.19,4366.71) ; v1@6912.86,3562.87 ccw(c6912.86,3576.15) 6922.25,3566.76 ccw(c6931.64,3557.37) v1@6918.36,3557.37 ; v1@6912.86,3566.87 ccw(c6912.86,3589.81) 6929.07,3573.59 ccw(c6945.29,3557.37) v1@6922.36,3557.37 ; v1@7190.19,4357.21 cw(c7190.19,4334.27) 7206.41,4350.49 cw(c7222.63,4366.71) v1@7199.69,4366.71 ; v1@7190.19,4361.21 cw(c7190.19,4347.93) 7199.58,4357.32 cw(c7208.97,4366.71) v1@7195.69,4366.71
  MidLayer2 w4: v1@5476.86,2778.87 cw(c5476.86,2755.94) 5493.07,2772.16 cw(c5509.29,2788.37) v1@5486.36,2788.37 ; v1@5476.86,2782.87 cw(c5476.86,2769.6) 5486.25,2778.99 cw(c5495.64,2788.37) v1@5482.36,2788.37 ; v1(5476.86,2788.37) 5573.52,2691.71 5631.86,2691.71 v1(5648.52,2675.04) ; v1@5639.02,2675.04 ccw(c5616.09,2675.04) 5632.31,2691.26 ccw(c5648.52,2707.48) v1@5648.52,2684.54 ; v1@5643.02,2675.04 ccw(c5629.75,2675.04) 5639.14,2684.43 ccw(c5648.52,2693.82) v1@5648.52,2680.54 ; v1@5890.19,3645.54 cw(c5890.19,3622.61) 5906.41,3638.82 cw(c5922.63,3655.04) v1@5899.69,3655.04 ; v1@5890.19,3649.54 cw(c5890.19,3636.26) 5899.58,3645.65 cw(c5908.97,3655.04) v1@5895.69,3655.04 ; v1(5890.19,3655.04) 5945.19,3600.04 6031.86,3600.04 6090.19,3541.71 v1(6123.52,3541.71) ; v1@6116.81,3534.99 ccw(c6100.59,3518.77) 6100.59,3541.71 ccw(c6100.59,3564.64) v1@6116.81,3548.43 ; v1@6119.64,3537.82 ccw(c6110.25,3528.43) 6110.25,3541.71 ccw(c6110.25,3554.99) v1@6119.64,3545.6 ; v1(6674.19,4416.71) 6725.19,4416.71 6766.86,4375.04 6951.19,4375.04 6976.19,4350.04 7015.19,4350.04 7023.52,4358.37 7048.52,4358.37 7090.19,4400.04 7190.19,4400.04 ; v1@6678.08,4412.82 cw(c6687.47,4403.43) 6687.47,4416.71 cw(c6687.47,4429.99) v1@6678.08,4420.6 ; v1@6680.91,4409.99 cw(c6697.13,4393.77) 6697.13,4416.71 cw(c6697.13,4439.64) v1@6680.91,4423.43 ; v1@7183.47,4373.43 ccw(c7167.26,4389.64) 7190.19,4389.64 ccw(c7213.13,4389.64) v1@7196.91,4373.43 ; v1@7186.3,4370.6 ccw(c7176.91,4379.99) 7190.19,4379.99 ccw(c7203.47,4379.99) v1@7194.08,4370.6 ; v1(7190.19,4366.71) 7190.19,4400.04 ; v1(7345.19,4412.04) 7333.19,4400.04 7190.19,4400.04
  Bottom Layer w4: v3@5666.89,3907.02 cw(c5670.04,3889.19) 5680.42,3904.02 ; v3@5672.98,3915.71 ccw(c5690.81,3918.86) 5680.42,3904.02 ; v1(5890.19,3655.04) 5920.04,3655.04 5928.02,3663.02 5928.02,3704.42 5918.48,3713.97 5918.48,3721.15 5935,3737.67 5935,3805 5928.1,3811.9 5920,3811.9 5910,3811.9 5841.96,3811.9 5783.7,3811.9 cw(c5783.7,3835.67) 5759.93,3835.67 ccw(c5744.33,3835.67) 5744.33,3851.27 cw(c5744.33,3875.04) 5720.56,3875.04 ccw(c5704.96,3875.04) 5704.96,3890.64 cw(c5704.96,3914.41) 5688.15,3897.6 5680.42,3904.02 ; v1@5894.08,3651.15 cw(c5903.47,3641.76) 5903.47,3655.04 cw(c5903.47,3668.32) v1@5894.08,3658.93 ; v1@5896.91,3648.32 cw(c5913.13,3632.11) 5913.13,3655.04 cw(c5913.13,3677.98) v1@5896.91,3661.76 ; v1(6287.86,3524.04) 6311.52,3547.71 6335.17,3547.71 6345.84,3558.37 6690.52,3558.37 6697.19,3551.71 6697.19,3533.37 6705.52,3525.04 6728.51,3525.04 6736.84,3516.71 6872.19,3516.71 v1(6912.86,3557.37) ; v1@6287.86,3529.54 ccw(c6287.86,3542.82) 6297.25,3533.43 ccw(c6306.64,3524.04) v1@6293.36,3524.04 ; v1@6287.86,3533.54 ccw(c6287.86,3556.48) 6304.07,3540.26 ccw(c6320.29,3524.04) v1@6297.36,3524.04 ; v1@6903.36,3557.37 cw(c6880.42,3557.37) 6896.64,3541.16 cw(c6912.86,3524.94) v1@6912.86,3547.87 ; v1@6907.36,3557.37 cw(c6894.08,3557.37) 6903.47,3547.99 cw(c6912.86,3538.6) v1@6912.86,3551.87 ; v1@7335.69,4412.04 cw(c7312.76,4412.04) 7328.97,4395.82 cw(c7345.19,4379.61) v1@7345.19,4402.54 ; v1@7339.69,4412.04 cw(c7326.41,4412.04) 7335.8,4402.65 cw(c7345.19,4393.26) v1@7345.19,4406.54 ; v1(7345.19,4412.04) 7328.19,4395.04 7328.19,4354.71 7357.86,4325.04 7420,4325.04 7456.84,4325 7465.21,4333.37 7595.48,4333.37 7620.48,4308.37 7743.19,4308.37 7752.19,4317.37 7752.19,4345.04 7754.86,4347.71 7821.01,4347.71 7840.19,4366.89 v2(7889.37,4366.89) ; v2@7881.59,4359.11 ccw(c7862.81,4340.33) 7862.81,4366.89 ccw(c7862.81,4393.45) v2@7881.59,4374.67 ; v2@7884.42,4361.94 ccw(c7872.47,4349.99) 7872.47,4366.89 ccw(c7872.47,4383.79) v2@7884.42,4371.84
DB_MEM.BUS_A17: U7.E7 U8.AB12 U16.42 U17.42 U61.105 | length 9892.8
  Top Layer w4: v3(5311.26,3835.67) U8.AB12@5330.94,3855.35 ; U8.AB12@5323.44,3855.35 cw(c5305.34,3855.35) 5318.14,3842.55 cw(c5330.94,3829.75) U8.AB12@5330.94,3847.85 ; U8.AB12@5323.6,3855.35 cw(c5305.88,3855.35) 5318.41,3842.82 cw(c5330.94,3830.29) U8.AB12@5330.94,3848.01 ; v1@5432.47,2826.66 cw(c5416.26,2810.44) 5439.19,2810.44 cw(c5462.13,2810.44) v1@5445.91,2826.66 ; v1@5435.3,2829.49 cw(c5425.91,2820.1) 5439.19,2820.1 cw(c5452.47,2820.1) v1@5443.08,2829.49 ; v1(5439.19,2833.37) 5439.19,2805.81 5450,2795 5450,2751.82 5466.61,2735.21 5483.69,2735.21 5493.21,2744.73 U61.105@5516.83,2744.73 5562.17,2744.73 v1(5594.52,2712.37) ; U61.105@5500.81,2741.9 ccw(c5493.98,2735.07) 5493.98,2744.73 ccw(c5493.98,2754.39) U61.105@5500.81,2747.56 ; U61.105@5532.85,2741.9 cw(c5539.68,2735.07) 5539.68,2744.73 cw(c5539.68,2754.39) U61.105@5532.85,2747.56 ; v1@5585.02,2712.37 ccw(c5562.09,2712.37) 5578.31,2728.59 ccw(c5594.52,2744.81) v1@5594.52,2721.87 ; v1@5589.02,2712.37 ccw(c5575.75,2712.37) 5585.14,2721.76 ccw(c5594.52,2731.15) v1@5594.52,2717.87 ; v1@6553.81,5031.32 cw(c6537.59,5015.11) 6560.52,5015.11 cw(c6583.46,5015.11) v1@6567.24,5031.32 ; v1@6556.64,5034.15 cw(c6547.25,5024.76) 6560.52,5024.76 cw(c6573.8,5024.76) v1@6564.41,5034.15 ; v1(6560.52,5038.04) 6560.52,4983.33 6552.19,4975 6552.19,4915.72 6560.19,4907.72 U17.42@6619.41,4907.72 ; U17.42@6596.19,4902.06 ccw(c6582.54,4888.4) 6582.54,4907.72 ccw(c6582.54,4927.03) U17.42@6596.19,4913.37 ; U16.42@7294.41,4907.72 v1@7345.53,4907.72 ; U16.42@7317.63,4902.06 cw(c7331.28,4888.4) 7331.28,4907.72 cw(c7331.28,4927.03) U16.42@7317.63,4913.37 ; 7329.81,4907.72 ccw(c7329.81,4931.76) v1@7346.81,4914.76 ; 7331.37,4907.72 cw(c7331.37,4885.89) v1@7346.81,4901.32 ; 7339.47,4907.72 ccw(c7339.47,4922.1) v1@7349.64,4911.93 ; 7341.03,4907.72 cw(c7341.03,4895.54) v1@7349.64,4904.15 ; v1@7345.86,4908.04 v1(7353.52,4908.04) ; v1@7790.19,4250.54 cw(c7790.19,4227.61) 7806.41,4243.82 cw(c7822.63,4260.04) v1@7799.69,4260.04 ; v1@7790.19,4254.54 cw(c7790.19,4241.26) 7799.58,4250.65 cw(c7808.97,4260.04) v1@7795.69,4260.04 ; v1(7790.19,4260.04) 7807.19,4243.04 7807.19,3658.71 7798.52,3650.04 7763.45,3614.97 7763.45,3516.55 7805,3475 7805,3348.38 7849.19,3304.19 7849.19,3048.37 v1(7825.86,3025.04) ; v1@7825.86,3030.54 ccw(c7825.86,3043.82) 7835.25,3034.43 ccw(c7844.64,3025.04) v1@7831.36,3025.04 ; v1@7825.86,3034.54 ccw(c7825.86,3057.48) 7842.07,3041.26 ccw(c7858.29,3025.04) v1@7835.36,3025.04 ; 5324.06,3848.47 cw(c5311.26,3861.28) 5311.26,3843.17 ccw(c5311.26,3861.28) 5324.06,3848.47 ; 5324.06,3848.47 ccw(c5336.87,3835.67) 5318.76,3835.67 cw(c5336.87,3835.67) 5324.06,3848.47
  Top Layer w8: v2(7810.63,4366.89) U7.E7@7830.32,4386.57 ; v2@7810.63,4375.89 ccw(c7810.63,4397.62) 7825.99,4382.25 ccw(c7841.36,4366.89) v2@7819.63,4366.89 ; U7.E7@7824.32,4386.57 cw(c7809.83,4386.57) 7820.07,4376.33 cw(c7830.32,4366.09) U7.E7@7830.32,4380.57
  MidLayer1 w4: v1@5223.28,3001.72 ccw(c5202.58,3022.42) 5231.86,3022.42 ; v1@5226.11,2998.89 ccw(c5212.24,3012.76) 5231.86,3012.76 ; v1(5230,2995) 5230,2993.56 5231.86,2991.71 5231.86,3076.86 5271.71,3116.71 5298.52,3116.71 5306.86,3125.04 5306.86,3147.02 5317.19,3157.35 5317.19,3200.04 5308.86,3208.37 5262.19,3208.37 5247.86,3222.71 5247.86,3494.04 5262.19,3508.37 5274.33,3508.37 5289.86,3523.9 5290.19,3523.9 5290.19,3541.71 5295.75,3547.27 5295.75,3660 5295.75,3670 5295.75,3718.62 5295.75,3812.16 ; 5231.86,3013.45 ccw(c5248.45,3013.45) v1@5236.72,3001.72 ; 5295.75,3798.23 5295.75,3812.16 ; 5299.87,3822.09 ccw(c5309.8,3812.16) 5295.75,3812.16 ; v3@5303.79,3835.02 cw(c5285.75,3833.44) 5299.62,3821.8 cw(c5313.49,3810.16) v3@5311.91,3828.2 ; v1(6560.52,5038.04) 6702.19,5038.04 6740.19,5000.04 6757.86,5000.04 6791.52,5033.71 6828.54,5033.71 6862.54,4999.71 6951.86,4999.71 6955.86,5003.71 7023.52,5003.71 7102.19,4925.04 7123.86,4925.04 7157.19,4891.71 7337.19,4891.71 v1(7353.52,4908.04) ; v1@6564.41,5034.15 cw(c6573.8,5024.76) 6573.8,5038.04 cw(c6573.8,5051.32) v1@6564.41,5041.93 ; v1@6567.24,5031.32 cw(c6583.46,5015.11) 6583.46,5038.04 cw(c6583.46,5060.98) v1@6567.24,5044.76 ; v1@7344.02,4908.04 cw(c7321.09,4908.04) 7337.31,4891.82 cw(c7353.52,4875.61) v1@7353.52,4898.54 ; v1@7348.02,4908.04 cw(c7334.75,4908.04) 7344.13,4898.65 cw(c7353.52,4889.26) v1@7353.52,4902.54 ; v1(7790.19,4260.04) 7831.86,4301.71 7831.86,4345.66 v2(7810.63,4366.89) ; v1@7790.19,4265.54 ccw(c7790.19,4278.82) 7799.58,4269.43 ccw(c7808.97,4260.04) v1@7795.69,4260.04 ; v1@7790.19,4269.54 ccw(c7790.19,4292.48) 7806.41,4276.26 ccw(c7822.63,4260.04) v1@7799.69,4260.04 ; v2@7810.63,4355.89 cw(c7810.63,4329.33) 7829.41,4348.11 cw(c7848.19,4366.89) v2@7821.63,4366.89 ; v2@7810.63,4359.89 cw(c7810.63,4342.99) 7822.58,4354.94 cw(c7834.53,4366.89) v2@7817.63,4366.89
  MidLayer2 w4: v1@5223.28,2988.28 cw(c5202.58,2967.58) 5231.86,2967.58 ; v1@5226.11,2991.11 cw(c5212.24,2977.24) 5231.86,2977.24 ; v1(5230,2995) 5231.86,2993.14 5231.86,2956.67 5215.19,2940 5215.19,2891.71 5273.52,2833.37 v1(5439.19,2833.37) ; 5231.86,2976.55 cw(c5248.45,2976.55) v1@5236.72,2988.28 ; v1@5432.47,2826.66 ccw(c5416.26,2810.44) 5416.26,2833.37 ccw(c5416.26,2856.31) v1@5432.47,2840.09 ; v1@5435.3,2829.49 ccw(c5425.91,2820.1) 5425.91,2833.37 ccw(c5425.91,2846.65) v1@5435.3,2837.26 ; v1(5594.52,2712.37) 5730.23,2712.37 5782.52,2660.08 5782.52,2632.52 5765.37,2615.37 v1(5739.52,2615.37) ; v1@5598.41,2708.49 cw(c5607.8,2699.1) 5607.8,2712.37 cw(c5607.8,2725.65) v1@5598.41,2716.26 ; v1@5601.24,2705.66 cw(c5617.46,2689.44) 5617.46,2712.37 cw(c5617.46,2735.31) v1@5601.24,2719.09 ; v1@5743.41,2611.49 cw(c5752.8,2602.1) 5752.8,2615.37 cw(c5752.8,2628.65) v1@5743.41,2619.26 ; v1@5746.24,2608.66 cw(c5762.46,2592.44) 5762.46,2615.37 cw(c5762.46,2638.31) v1@5746.24,2622.09 ; v1(7353.52,4908.04) 7433.04,4908.04 7482,4957 7613.58,4957 7645.54,4925.04 7821.86,4925.04 v1(7923.52,4823.37) ; v1@7357.41,4904.15 cw(c7366.8,4894.76) 7366.8,4908.04 cw(c7366.8,4921.32) v1@7357.41,4911.93 ; v1@7360.24,4901.32 cw(c7376.46,4885.11) 7376.46,4908.04 cw(c7376.46,4930.98) v1@7360.24,4914.76 ; v1@7914.02,4823.37 ccw(c7891.09,4823.37) 7907.31,4839.59 ccw(c7923.52,4855.81) v1@7923.52,4832.87 ; v1@7918.02,4823.37 ccw(c7904.75,4823.37) 7914.14,4832.76 ccw(c7923.52,4842.15) v1@7923.52,4828.87
  Bottom Layer w4: v1(5739.52,2615.37) 5764.52,2615.37 5810.52,2569.37 6379.19,2569.37 6425.52,2523.04 6548.9,2523.04 6592.23,2566.37 6848.19,2566.37 6892.19,2610.37 6963.56,2610.37 6969.9,2616.71 7119.52,2616.71 7386.19,2883.37 7684.19,2883.37 v1(7825.86,3025.04) ; v1@5743.41,2611.49 cw(c5752.8,2602.1) 5752.8,2615.37 cw(c5752.8,2628.65) v1@5743.41,2619.26 ; v1@5746.24,2608.66 cw(c5762.46,2592.44) 5762.46,2615.37 cw(c5762.46,2638.31) v1@5746.24,2622.09 ; v1@7790.19,4250.54 cw(c7790.19,4227.61) 7806.41,4243.82 cw(c7822.63,4260.04) v1@7799.69,4260.04 ; v1@7790.19,4254.54 cw(c7790.19,4241.26) 7799.58,4250.65 cw(c7808.97,4260.04) v1@7795.69,4260.04 ; v1(7790.19,4260.04) 7808.52,4241.71 8007.86,4241.71 8083.52,4317.37 8083.52,4663.37 v1(7923.52,4823.37) ; v1@7816.36,3025.04 cw(c7793.42,3025.04) 7809.64,3008.82 cw(c7825.86,2992.61) v1@7825.86,3015.54 ; v1@7820.36,3025.04 cw(c7807.08,3025.04) 7816.47,3015.65 cw(c7825.86,3006.26) v1@7825.86,3019.54 ; v1@7923.52,4813.87 cw(c7923.52,4790.94) 7939.74,4807.16 cw(c7955.96,4823.37) v1@7933.02,4823.37 ; v1@7923.52,4817.87 cw(c7923.52,4804.6) 7932.91,4813.99 cw(c7942.3,4823.37) v1@7929.02,4823.37
DB_MEM.BUS_A18: U7.B3 U8.C17 U16.43 U17.43 | length 4420.5
  Top Layer w4: v1@5559.47,4885.99 cw(c5543.26,4869.77) 5566.19,4869.77 cw(c5589.13,4869.77) v1@5572.91,4885.99 ; v1@5562.3,4888.82 cw(c5552.91,4879.43) 5566.19,4879.43 cw(c5579.47,4879.43) v1@5570.08,4888.82 ; v1(5566.19,4892.71) 5566.19,4787.98 5551.66,4773.45 5551.66,4724.74 5551.66,4720 5551.66,4710 5551.66,4643.27 ; v1(6506.86,5168.71) 6638.71,5168.71 6656.86,5150.56 6656.86,4947.21 ; v1@6510.75,5164.82 cw(c6520.14,5155.43) 6520.14,5168.71 cw(c6520.14,5181.99) v1@6510.75,5172.6 ; v1@6513.57,5161.99 cw(c6529.79,5145.77) 6529.79,5168.71 cw(c6529.79,5191.64) v1@6513.57,5175.43 ; U17.43@6619.41,4939.21 6648.86,4939.21 ; U17.43@6636.97,4939.21 ccw(c6642.79,4947.68) 6650.06,4940.41 ; U17.43@6639.24,4942.51 ccw(c6645.56,4951.71) 6653.46,4943.81 ; U17.43@6641.5,4945.8 ccw(c6648.33,4955.74) 6656.86,4947.21 ; U17.43@6644.38,4936.2 cw(c6648.86,4934.38) 6648.86,4939.21 ; U17.43@6644.38,4942.23 ccw(c6648.86,4944.05) 6648.86,4939.21 ; U16.43@7294.41,4939.21 7342.7,4939.21 v1(7353.52,4950.04) ; U16.43@7317.63,4933.56 cw(c7331.28,4919.9) 7331.28,4939.21 cw(c7331.28,4958.53) U16.43@7317.63,4944.87 ; 5540.33,4615.92 ccw(c5512.98,4643.27) 5551.66,4643.27 ; 5540.33,4615.92 ccw(c5512.98,4643.27) 5551.66,4643.27 ; 5540.33,4615.92 ccw(c5552.86,4603.39) 5535.14,4603.39 cw(c5552.86,4603.39) 5540.33,4615.92 ; 5540.33,4615.92 cw(c5527.8,4628.45) 5527.8,4610.73 ccw(c5527.8,4628.45) 5540.33,4615.92 ; 6648.86,4939.21 6656.86,4947.21
  Top Layer w8: U7.B3@7948.43,4544.06 v2(7968.11,4563.74) ; U7.B3@7948.43,4550.06 ccw(c7948.43,4564.54) 7958.67,4554.3 ccw(c7968.91,4544.06) U7.B3@7954.43,4544.06 ; v2@7959.11,4563.74 cw(c7937.38,4563.74) 7952.75,4548.38 cw(c7968.11,4533.01) v2@7968.11,4554.74
  MidLayer1 w4: v1@5559.47,4899.43 ccw(c5548.89,4910.01) 5563.86,4910.01 ; 5563.86,4911.62 ccw(c5585.1,4911.62) v1@5570.08,4896.6 ; 5563.86,4921.28 ccw(c5594.76,4921.28) v1@5572.91,4899.43 ; v1(5566.19,4892.71) 5563.86,4895.04 5563.86,4948.1 5616.64,5000.88 5640.8,5025.04 5856.86,5025.04 5873.52,5041.71 5873.52,5108.37 5898.52,5133.37 6471.52,5133.37 v1(6506.86,5168.71) ; v1@6497.36,5168.71 cw(c6474.42,5168.71) 6490.64,5152.49 cw(c6506.86,5136.27) v1@6506.86,5159.21 ; v1@6501.36,5168.71 cw(c6488.08,5168.71) 6497.47,5159.32 cw(c6506.86,5149.93) v1@6506.86,5163.21
  MidLayer2 w4: v1(7353.52,4950.04) 7395.19,4991.71 7798.52,4991.71 7965.19,4825.04 7988,4802.23 7988,4595 7980,4587 7980,4575.63 v2(7968.11,4563.74) ; v1@7353.52,4955.54 ccw(c7353.52,4968.82) 7362.91,4959.43 ccw(c7372.3,4950.04) v1@7359.02,4950.04 ; v1@7353.52,4959.54 ccw(c7353.52,4982.48) 7369.74,4966.26 ccw(c7385.96,4950.04) v1@7363.02,4950.04
  Bottom Layer w4: v1(6506.86,5168.71) 6522.19,5184.04 6833.21,5184.04 6858.88,5158.37 6918.17,5158.37 6926.5,5150.04 7050,5150.04 7067.19,5150.04 7142.56,5150.04 7234.23,5058.37 7270,5058.37 7273.52,5058.37 7353.52,4978.37 v1(7353.52,4950.04) ; v1@7346.81,4956.76 ccw(c7330.59,4972.98) 7353.52,4972.98 ccw(c7376.46,4972.98) v1@7360.24,4956.76 ; v1@7349.64,4953.93 ccw(c7340.25,4963.32) 7353.52,4963.32 ccw(c7366.8,4963.32) v1@7357.41,4953.93
DB_MEM.BUS_A19: U7.C4 U8.B17 U16.44 U17.44 | length 5840.3
  Top Layer w4: 5543.3,4725.04 5543.3,4724.74 ; v1@5567.81,5194.32 cw(c5551.59,5178.11) 5574.52,5178.11 cw(c5597.46,5178.11) v1@5581.24,5194.32 ; v1@5570.64,5197.15 cw(c5561.25,5187.76) 5574.52,5187.76 cw(c5587.8,5187.76) v1@5578.41,5197.15 ; v1(5574.52,5201.04) 5574.52,5097.67 5548.52,5071.67 5548.52,4836.35 5556.86,4828.02 5556.86,4789.96 5543.3,4776.41 5543.3,4724.74 ; v1@6600.59,5009.57 cw(c6588.4,4995.71) 6606.86,4995.71 ; v1@6603.23,5012.58 cw(c6596.17,5004.55) 6606.86,5004.55 cw(c6617.54,5004.55) v1@6610.49,5012.58 ; v1(6606.86,5016.71) 6606.86,4995.71 ; v1@6613.13,5009.57 ccw(c6625.32,4995.71) 6606.86,4995.71 ; U17.44@6616.09,4977.99 ccw(c6613.73,4983.16) 6619.41,4983.16 ; U17.44@6619.41,4970.71 6619.41,4983.16 ; U17.44@6622.73,4977.99 cw(c6625.09,4983.16) 6619.41,4983.16 ; U16.44@7294.41,4970.71 7328.86,4970.71 ; U16.44@7318.16,4965.64 cw(c7328.86,4956.88) 7328.86,4970.71 ; U16.44@7318.16,4975.78 ccw(c7328.86,4984.53) 7328.86,4970.71 ; v1@7330.14,5031.66 cw(c7313.92,5015.44) 7336.86,5015.44 cw(c7359.79,5015.44) v1@7343.57,5031.66 ; v1@7332.97,5034.49 cw(c7323.58,5025.1) 7336.86,5025.1 cw(c7350.14,5025.1) v1@7340.75,5034.49 ; v1(7336.86,5038.37) 7336.86,4978.71 7328.86,4970.71 ; 5540.33,4655.29 ccw(c5533.15,4662.47) 5543.3,4662.47 ; 5540.33,4655.29 ccw(c5533.15,4662.47) 5543.3,4662.47 ; 5540.33,4655.29 cw(c5527.8,4667.83) 5527.8,4650.1 ccw(c5527.8,4667.83) 5540.33,4655.29 ; 5540.33,4655.29 ccw(c5552.86,4642.76) 5535.14,4642.76 cw(c5552.86,4642.76) 5540.33,4655.29 ; 5543.3,4662.47 5543.3,4710 5543.3,4720 5543.3,4724.74 ; 6606.86,4995.71 6619.41,4983.16
  Top Layer w8: U7.C4@7909.06,4504.69 v2(7928.74,4524.37) ; U7.C4@7909.06,4510.69 ccw(c7909.06,4525.17) 7919.3,4514.93 ccw(c7929.54,4504.69) U7.C4@7915.06,4504.69 ; v2@7919.74,4524.37 cw(c7898.01,4524.37) 7913.38,4509.01 cw(c7928.74,4493.64) v2@7928.74,4515.37
  MidLayer1 w4: v1(6606.86,5016.71) 6698.52,5016.71 6731.86,4983.37 6952.86,4983.37 6965.19,4995.71 7020.21,4995.71 7099.21,4916.71 7110.19,4916.71 7143.52,4883.37 7365.19,4883.37 7373.52,4891.71 7373.52,5001.71 v1(7336.86,5038.37) 7378.37,5038.37 7384.52,5044.52 v1(7384.52,5097.37) ; v1@6610.75,5012.82 cw(c6620.14,5003.43) 6620.14,5016.71 cw(c6620.14,5029.99) v1@6610.75,5020.6 ; v1@6613.57,5009.99 cw(c6629.79,4993.77) 6629.79,5016.71 cw(c6629.79,5039.64) v1@6613.57,5023.43 ; v1@7336.86,5028.87 cw(c7336.86,5005.94) 7353.07,5022.16 cw(c7369.29,5038.37) v1@7346.36,5038.37 ; v1@7336.86,5032.87 cw(c7336.86,5019.6) 7346.25,5028.99 cw(c7355.64,5038.37) v1@7342.36,5038.37 ; v1@7340.75,5034.49 cw(c7350.14,5025.1) 7350.14,5038.37 cw(c7350.14,5051.65) v1@7340.75,5042.26 ; v1@7343.57,5031.66 cw(c7359.79,5015.44) 7359.79,5038.37 cw(c7359.79,5061.31) v1@7343.57,5045.09 ; v1@7377.81,5090.66 cw(c7361.59,5074.44) 7384.52,5074.44 cw(c7407.46,5074.44) v1@7391.24,5090.66 ; v1@7380.64,5093.49 cw(c7371.25,5084.1) 7384.52,5084.1 cw(c7397.8,5084.1) v1@7388.41,5093.49
  MidLayer2 w4: v1(6070,5290) 6475,5290 6495,5310 6600,5310 6635,5275 7206.9,5275 v1(7384.52,5097.37) v1@7384.52,5101.37 ; v1@6073.89,5286.11 cw(c6083.28,5276.72) 6083.28,5290 cw(c6083.28,5303.28) v1@6073.89,5293.89 ; v1@6076.72,5283.28 cw(c6092.93,5267.06) 6092.93,5290 cw(c6092.93,5312.93) v1@6076.72,5296.72 ; v1@7336.86,5028.87 cw(c7336.86,5005.94) 7353.07,5022.16 cw(c7369.29,5038.37) v1@7346.36,5038.37 ; v1@7336.86,5032.87 cw(c7336.86,5019.6) 7346.25,5028.99 cw(c7355.64,5038.37) v1@7342.36,5038.37 ; v1(7336.86,5038.37) 7365.23,5010 7802.86,5010 8040,4772.86 8040,4608.56 8040.19,4608.37 8015.19,4583.37 7993.37,4583.37 7988,4578 7988,4551 7981,4544 7948.37,4544 ; v1@7375.02,5097.37 ccw(c7352.09,5097.37) 7368.31,5113.59 ccw(c7384.52,5129.81) v1@7384.52,5106.87 ; v1@7379.02,5097.37 ccw(c7365.75,5097.37) 7375.14,5106.76 ccw(c7384.52,5116.15) v1@7384.52,5102.87 ; v2(7928.74,4524.37) 7948.37,4544 ; v2@7928.74,4531.37 ccw(c7928.74,4548.27) 7940.69,4536.32 ccw(c7952.64,4524.37) v2@7935.74,4524.37 ; v2@7928.74,4535.37 ccw(c7928.74,4561.93) 7947.52,4543.15 ccw(c7966.3,4524.37) v2@7939.74,4524.37 ; 7948.52,4544.15 7948.37,4544
  Bottom Layer w4: v1(5574.52,5201.04) 5639.86,5266.37 6046.37,5266.37 v1(6070,5290) ; v1@5574.52,5206.54 ccw(c5574.52,5219.82) 5583.91,5210.43 ccw(c5593.3,5201.04) v1@5580.02,5201.04 ; v1@5574.52,5210.54 ccw(c5574.52,5233.48) 5590.74,5217.26 ccw(c5606.96,5201.04) v1@5584.02,5201.04 ; v1@6060.5,5290 cw(c6037.56,5290) 6053.78,5273.78 cw(c6070,5257.56) v1@6070,5280.5 ; v1@6064.5,5290 cw(c6051.22,5290) 6060.61,5280.61 cw(c6070,5271.22) v1@6070,5284.5
DB_MEM.BUS_A20: U7.D5 U8.J26 U16.28 U17.28 | length 3585.2
  Top Layer w4: U8.J26@5882.13,4367.17 5910,4367.17 5920,4367.17 5924.74,4367.17 5940.75,4367.16 5973.54,4334.37 6057.86,4334.37 v1(6090.19,4366.71) ; U8.J26@5887.32,4361.97 cw(c5899.85,4349.44) 5899.85,4367.17 cw(c5899.85,4384.89) U8.J26@5887.32,4372.36 ; U8.J26@5887.43,4361.86 cw(c5900.23,4349.06) 5900.23,4367.17 cw(c5900.23,4385.27) U8.J26@5887.43,4372.47 ; v1@6080.69,4366.71 cw(c6057.76,4366.71) 6073.97,4350.49 cw(c6090.19,4334.27) v1@6090.19,4357.21 ; v1@6084.69,4366.71 cw(c6071.41,4366.71) 6080.8,4357.32 cw(c6090.19,4347.93) v1@6090.19,4361.21 ; v1@6571.09,4460.14 cw(c6587.09,4444.14) 6587.09,4466.77 ; v1(6572.86,4458.37) 6581.25,4466.77 U17.28@6619.41,4466.77 ; v1@6573.92,4457.31 cw(c6596.75,4434.48) U17.28@6596.75,4466.77 ; v1@6576.75,4454.49 cw(c6606.41,4424.82) U17.28@6606.41,4466.77 ; v1@6579.57,4451.66 cw(c6616.06,4415.17) U17.28@6616.06,4466.77 ; U17.28@6596.19,4461.12 ccw(c6582.54,4447.46) 6582.54,4466.77 ccw(c6582.54,4486.09) U17.28@6596.19,4472.43 ; U16.28@7294.41,4466.77 7337.19,4466.77 7345.19,4458.77 ; U16.28@7317.63,4461.12 cw(c7331.28,4447.46) 7331.28,4466.77 cw(c7331.28,4486.09) U16.28@7317.63,4472.43 ; v1@7340.19,4449.78 ccw(c7334.62,4458.77) 7345.19,4458.77 ; v1(7345.19,4441.71) 7345.19,4458.77 ; v1@7350.19,4449.78 cw(c7355.76,4458.77) 7345.19,4458.77
  Top Layer w8: U7.D5@7869.69,4459.32 cw(c7869.69,4444.83) 7879.93,4455.07 cw(c7890.17,4465.32) U7.D5@7875.69,4465.32 ; U7.D5@7869.69,4465.32 v2(7889.37,4445.63) ; v2@7880.37,4445.63 ccw(c7858.64,4445.63) 7874.01,4460.99 ccw(c7889.37,4476.36) v2@7889.37,4454.63
  MidLayer2 w4: v1(6090.19,4366.71) 6123.52,4366.71 6148.52,4391.71 6260.19,4391.71 6273.52,4378.37 6468.65,4378.37 6548.65,4458.37 v1(6572.86,4458.37) 6636.67,4458.37 6645,4450.04 6748.52,4450.04 6781.86,4416.71 6823.52,4416.71 6840.19,4400.04 7015.19,4400.04 7023.52,4391.71 7048.52,4391.71 7065.19,4408.37 7311.86,4408.37 v1(7345.19,4441.71) ; v1@6094.08,4362.82 cw(c6103.47,4353.43) 6103.47,4366.71 cw(c6103.47,4379.99) v1@6094.08,4370.6 ; v1@6096.91,4359.99 cw(c6113.13,4343.77) 6113.13,4366.71 cw(c6113.13,4389.64) v1@6096.91,4373.43 ; v1@6566.14,4451.66 ccw(c6549.92,4435.44) 6549.92,4458.37 ccw(c6549.92,4481.31) v1@6566.14,4465.09 ; v1@6568.97,4454.49 ccw(c6559.58,4445.1) 6559.58,4458.37 ccw(c6559.58,4471.65) v1@6568.97,4462.26 ; v1@6576.75,4454.49 cw(c6586.14,4445.1) 6586.14,4458.37 cw(c6586.14,4471.65) v1@6576.75,4462.26 ; v1@6579.57,4451.66 cw(c6595.79,4435.44) 6595.79,4458.37 cw(c6595.79,4481.31) v1@6579.57,4465.09 ; v1@7335.69,4441.71 cw(c7312.76,4441.71) 7328.97,4425.49 cw(c7345.19,4409.27) v1@7345.19,4432.21 ; v1@7339.69,4441.71 cw(c7326.41,4441.71) 7335.8,4432.32 cw(c7345.19,4422.93) v1@7345.19,4436.21
  Bottom Layer w4: v1@7345.19,4432.21 cw(c7345.19,4409.27) 7361.41,4425.49 cw(c7377.63,4441.71) v1@7354.69,4441.71 ; v1@7345.19,4436.21 cw(c7345.19,4422.93) 7354.58,4432.32 cw(c7363.97,4441.71) v1@7350.69,4441.71 ; v1(7345.19,4441.71) 7365.19,4421.71 7365.19,4383.37 7407.19,4341.37 7440.19,4341.37 7556.86,4458.04 7556.86,4566.71 7540.19,4583.37 7540.19,4691.71 7565.19,4716.71 7606.86,4716.71 7656.86,4666.71 7656.86,4569.04 7681.86,4544.04 7848.52,4544.04 7868.52,4524.04 7868.52,4466.48 v2(7889.37,4445.63) ; v2@7878.37,4445.63 ccw(c7851.81,4445.63) 7870.59,4464.41 ccw(c7889.37,4483.19) v2@7889.37,4456.63 ; v2@7882.37,4445.63 ccw(c7865.47,4445.63) 7877.42,4457.58 ccw(c7889.37,4469.53) v2@7889.37,4452.63
DB_MEM.BUS_A21: U7.D4 U8.J22 | length 2792
  Top Layer w4: U8.J22@5724.65,4367.17 v3(5744.33,4386.85) ; U8.J22@5724.65,4374.51 ccw(c5724.65,4392.23) 5737.18,4379.7 ccw(c5749.71,4367.17) U8.J22@5731.99,4367.17 ; U8.J22@5724.65,4374.67 ccw(c5724.65,4392.77) 5737.45,4379.97 ccw(c5750.25,4367.17) U8.J22@5732.15,4367.17 ; 5731.53,4374.05 cw(c5744.33,4361.24) 5744.33,4379.35 ccw(c5744.33,4361.24) 5731.53,4374.05 ; 5731.53,4374.05 ccw(c5718.72,4386.85) 5736.83,4386.85 cw(c5718.72,4386.85) 5731.53,4374.05
  Top Layer w8: U7.D4@7869.69,4504.69 v2(7889.37,4524.37) ; U7.D4@7869.69,4510.69 ccw(c7869.69,4525.17) 7879.93,4514.93 ccw(c7890.17,4504.69) U7.D4@7875.69,4504.69 ; v2@7880.37,4524.37 cw(c7858.64,4524.37) 7874.01,4509.01 cw(c7889.37,4493.64) v2@7889.37,4515.37
  MidLayer1 w4: v3@5744.98,4394.32 ccw(c5746.56,4412.36) 5758.2,4398.49 ccw(c5769.84,4384.62) v3@5751.8,4386.2 ; 5757.91,4398.24 cw(c5767.84,4388.31) 5767.84,4402.36 5861.38,4402.36 5910,4402.36 5920,4402.36 5966.98,4402.36 5970,4405.37 6021.86,4405.37 6043.86,4427.37 6043.86,4458.37 6060.52,4475.04 6081.86,4475.04 6206.86,4600.04 6314.19,4600.04 6331.86,4617.71 6530.86,4617.71 6590.19,4558.37 6706.86,4558.37 6740.19,4591.71 6923.52,4591.71 6931.86,4600.04 6931.86,4641.71 v1(6921.19,4652.37)
  MidLayer2 w4: v1(6921.19,4652.37) 6916.86,4648.04 6916.86,4644.71 6923.52,4638.04 7194.35,4638.04 7265.69,4709.37 7581.86,4709.37 7616.19,4675.04 7774.86,4675.04 7791.52,4658.37 7791.52,4546.04 7793.52,4544.04 7869.86,4544.04 7873.52,4540.37 7873.52,4540.22 v2(7889.37,4524.37)
DB_MEM.BUS_A22: U7.C5 U8.L22 | length 2823.5
  Top Layer w4: U8.L22@5724.65,4288.43 v3(5744.33,4308.11) ; U8.L22@5724.65,4295.77 ccw(c5724.65,4313.49) 5737.18,4300.96 ccw(c5749.71,4288.43) U8.L22@5731.99,4288.43 ; U8.L22@5724.65,4295.93 ccw(c5724.65,4314.03) 5737.45,4301.23 ccw(c5750.25,4288.43) U8.L22@5732.15,4288.43 ; 5731.53,4295.31 cw(c5744.33,4282.5) 5744.33,4300.61 ccw(c5744.33,4282.5) 5731.53,4295.31 ; 5731.53,4295.31 ccw(c5718.72,4308.11) 5736.83,4308.11 cw(c5718.72,4308.11) 5731.53,4295.31
  Top Layer w8: U7.C5@7909.06,4459.32 cw(c7909.06,4444.83) 7919.3,4455.07 cw(c7929.54,4465.32) U7.C5@7915.06,4465.32 ; U7.C5@7909.06,4465.32 v2(7928.74,4445.63) ; v2@7919.74,4445.63 ccw(c7898.01,4445.63) 7913.38,4460.99 ccw(c7928.74,4476.36) v2@7928.74,4454.63
  MidLayer1 w4: v3@5744.98,4315.58 ccw(c5746.56,4333.62) 5758.2,4319.75 ccw(c5769.84,4305.88) v3@5751.8,4307.46 ; 5757.91,4319.5 cw(c5767.84,4309.57) 5767.84,4323.62 5861.38,4323.62 5910,4323.62 5920,4323.62 5988.77,4323.62 5998.52,4333.37 6140.19,4333.37 6214.19,4407.37 6268.5,4407.37 6276.84,4399.04 6404.86,4399.04 v1(6406.86,4397.04) ; 6379.09,4399.04 cw(c6379.09,4369.28) v1@6400.14,4390.32 ; v1@6400.14,4403.76 cw(c6388.75,4415.15) 6388.75,4399.04 cw(c6388.75,4378.93) v1@6402.97,4393.15
  MidLayer2 w4: v1(6406.86,4397.04) 6476,4397.04 6555,4476.04 6630.86,4476.04 6648.52,4458.37 6831.86,4458.37 6865.19,4425.04 6965.19,4425.04 6981.86,4441.71 6981.86,4519.08 6988.15,4525.37 7149.88,4525.37 7208.54,4466.71 7272.17,4466.71 7281.5,4476.04 7898.33,4476.04 v2(7928.74,4445.63) ; v1@6410.75,4393.15 cw(c6420.14,4383.76) 6420.14,4397.04 cw(c6420.14,4410.32) v1@6410.75,4400.93 ; v1@6413.57,4390.32 cw(c6429.79,4374.11) 6429.79,4397.04 cw(c6429.79,4419.98) v1@6413.57,4403.76 ; v2@7917.74,4445.63 ccw(c7891.18,4445.63) 7909.96,4464.41 ccw(c7928.74,4483.19) v2@7928.74,4456.63 ; v2@7921.74,4445.63 ccw(c7904.84,4445.63) 7916.79,4457.58 ccw(c7928.74,4469.53) v2@7928.74,4452.63
DB_MEM.BUS_A23: U7.B8 U8.N24 | length 2749.3
  Top Layer w4: U8.N24@5803.39,4217.03 ccw(c5803.39,4234.75) 5815.92,4222.22 ; U8.N24@5810.73,4209.69 cw(c5828.45,4209.69) 5815.92,4222.22 ; v1@5943.68,4216.55 ccw(c5938.66,4225.04) 5948.52,4225.04 ; v1(5948.52,4208.37) 5948.52,4225.04 ; v1@5953.36,4216.55 cw(c5958.39,4225.04) 5948.52,4225.04 ; 5815.92,4222.22 cw(c5843.27,4194.87) 5843.27,4233.55 5910,4233.55 5920,4233.55 5924.74,4233.55 5940.02,4233.55 5948.52,4225.04
  Top Layer w8: U7.B8@7948.43,4341.2 cw(c7948.43,4326.72) 7958.67,4336.96 cw(c7968.91,4347.2) U7.B8@7954.43,4347.2 ; U7.B8@7948.43,4347.2 v2(7968.11,4327.52) ; v2@7959.11,4327.52 ccw(c7937.38,4327.52) 7952.75,4342.88 ccw(c7968.11,4358.25) v2@7968.11,4336.52
  MidLayer2 w4: v1@5952.41,4204.49 cw(c5961.8,4195.1) 5961.8,4208.37 cw(c5961.8,4221.65) v1@5952.41,4212.26 ; v1@5955.24,4201.66 cw(c5971.46,4185.44) 5971.46,4208.37 cw(c5971.46,4231.31) v1@5955.24,4215.09 ; 6004.19,4216.71 6012.52,4225.04 ; 7946.22,4344.01 ccw(c7961.25,4359.04) v2@7965.77,4338.27 ; 7951.4,4338.83 ccw(c7963.1,4350.53) v2@7966.62,4334.36 ; 7953.15,4337.08 cw(c7943.59,4327.52) v2@7957.11,4327.52 ; 7956.58,4333.65 ccw(c7964.96,4342.02) v2@7967.47,4330.45 ; v2(7968.11,4327.52) 7962.26,4333.37 7956.86,4333.37 7943.52,4346.71 7873.52,4346.71 7815.19,4288.37 7815.19,4225.04 7731.86,4141.71 7525,4141.71 7470.54,4141.71 7436.88,4108.04 7315.52,4108.04 7306.86,4116.71 7273.52,4150.04 7206.86,4150.04 7181.86,4125.04 7023.52,4125.04 7015.19,4133.37 6848.52,4133.37 6823.52,4158.37 6698.52,4158.37 6680.52,4176.37 6630.52,4176.37 6603.15,4176.37 6588.15,4191.37 6482.19,4191.37 6440.19,4233.37 6323.52,4233.37 6303.19,4213.04 6248.52,4213.04 6218.86,4183.37 6168.86,4183.37 6110.52,4241.71 6062.21,4241.71 6053.88,4250.04 6020.86,4250.04 6012.52,4241.71 6012.52,4225.04 ; v1@5956.86,4208.37 5952.69,4204.21 5948.52,4200.04 v1(5948.52,4208.37) v1@5956.86,4208.37 ; v1@5956.86,4208.37 5995.86,4208.37 6012.52,4225.04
